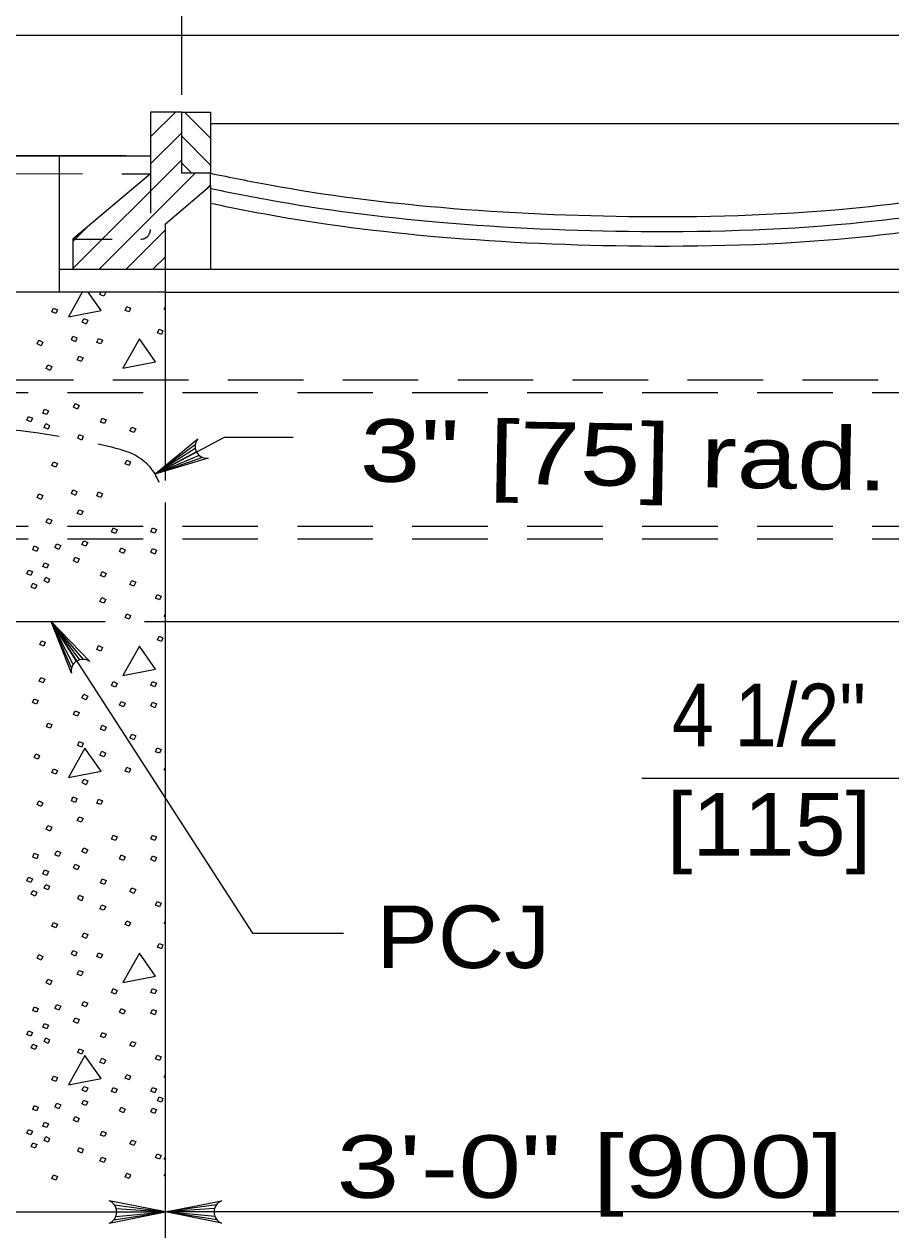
# Model space of a CAD drawing. Extents: x -1431.2 to -1397.2, y -1045.1 to -1001.1.
# Drawn here: x -1420.547 to -1418.346, y -1019.579 to -1016.517 of the extents above; entities that cross this region are included whole.
import ezdxf
from ezdxf.enums import TextEntityAlignment as Align

# ---------------------------------------------------------------- set-up
doc = ezdxf.new("R2010")
doc.units = 0
doc.header["$LTSCALE"] = 0.064
for name, pattern in [('LONG_DASHED', [7.5, 6, -1.5]), ('MEDIUM_DASHED', [4.5, 3, -1.5]), ('SHORT_DASHED', [2.7, 1.5, -1.2])]:
    doc.linetypes.add(name, pattern=pattern)
doc.layers.add('1', color=7, linetype='Continuous', lineweight=13)

msp = doc.modelspace()

# ---------------------------------------------------------------- linework, layer by layer
at = {"layer": '1'}
for p, q in [((-1420.147, -1016.69683), (-1420.147, -1016.11292)), ((-1420.22625, -1016.80383), (-1420.163, -1016.74058)), ((-1420.07358, -1016.80692), (-1420.14, -1016.74058)), ((-1420.22625, -1016.87233), (-1420.147, -1016.793)), ((-1420.07358, -1016.8755), (-1420.147, -1016.80208)), ((-1420.42342, -1017.13792), (-1420.147, -1016.8615)), ((-1420.12158, -1016.896), (-1420.147, -1016.87058)), ((-1420.35675, -1017.13975), (-1420.11292, -1016.896)), ((-1420.07358, -1016.896), (-1420.147, -1016.896)), ((-1420.08667, -1016.93817), (-1420.07358, -1016.92508)), ((-1420.42342, -1017.06942), (-1420.38458, -1017.03067)), ((-1420.28833, -1017.13975), (-1420.18825, -1017.03975)), ((-1420.21983, -1017.13975), (-1420.18825, -1017.10817)), ((-1420.11267, -1017.58558), (-1420.21558, -1017.65967)), ((-1420.11242, -1017.59525), (-1420.21558, -1017.65967)), ((-1420.10942, -1017.60375), (-1420.21558, -1017.65967)), ((-1420.10217, -1017.61267), (-1420.21558, -1017.65967)), ((-1420.09417, -1017.61767), (-1420.21558, -1017.65967)), ((-1420.41392, -1018.13508), (-1420.47867, -1018.03408)), ((-1420.42225, -1018.14308), (-1420.47867, -1018.03408)), ((-1420.4265, -1018.1515), (-1420.47867, -1018.03408)), ((-1420.40575, -1018.13142), (-1420.47867, -1018.03408)), ((-1420.39617, -1018.13033), (-1420.47867, -1018.03408)), ((-1418.97808, -1018.43242), (-1417.79208, -1018.43242)), ((-1421.59133, -1019.53367), (-1420.18825, -1019.53367)), ((-1420.31917, -1019.55367), (-1420.18825, -1019.53367)), ((-1420.31758, -1019.51558), (-1420.18825, -1019.53367)), ((-1420.31417, -1019.54533), (-1420.18825, -1019.53367)), ((-1420.31325, -1019.52458), (-1420.18825, -1019.53367)), ((-1420.31192, -1019.53367), (-1420.18825, -1019.53367)), ((-1420.05892, -1019.51558), (-1420.18825, -1019.53367)), ((-1420.06325, -1019.52458), (-1420.18825, -1019.53367)), ((-1417.79208, -1019.53367), (-1420.18825, -1019.53367)), ((-1420.06458, -1019.53367), (-1420.18825, -1019.53367)), ((-1420.06233, -1019.54533), (-1420.18825, -1019.53367)), ((-1420.05733, -1019.55367), (-1420.18825, -1019.53367))]:
    msp.add_line(p, q, dxfattribs=at)
at = {"layer": '1', "lineweight": 25}
for p, q in [((-1420.07358, -1016.76975), (-1417.85858, -1016.76975)), ((-1420.28933, -1016.85133), (-1421.04217, -1016.85133)), ((-1420.45767, -1017.19833), (-1420.45767, -1016.85133)), ((-1420.07358, -1016.927), (-1420.07358, -1017.13975)), ((-1420.45767, -1017.13975), (-1420.42342, -1017.13975)), ((-1420.18825, -1017.13975), (-1417.85858, -1017.13975)), ((-1420.18825, -1017.19833), (-1417.79208, -1017.19833)), ((-1420.18825, -1017.67583), (-1420.18825, -1017.19833)), ((-1420.18825, -1019.77192), (-1420.18825, -1017.73225)), ((-1420.18825, -1018.03408), (-1417.79208, -1018.03408))]:
    msp.add_line(p, q, dxfattribs=at)
at = {"layer": '1', "linetype": 'LONG_DASHED', "lineweight": 25}
for p, q in [((-1421.267, -1016.89492), (-1420.22625, -1016.89758)), ((-1420.72517, -1018.03408), (-1420.18825, -1018.03408))]:
    msp.add_line(p, q, dxfattribs=at)
at = {"layer": '1', "linetype": 'SHORT_DASHED', "lineweight": 25}
for p, q in [((-1420.22625, -1016.89758), (-1420.22625, -1017.03908)), ((-1420.42342, -1017.06325), (-1420.25042, -1017.06325))]:
    msp.add_line(p, q, dxfattribs=at)
at = {"layer": '1', "linetype": 'MEDIUM_DASHED'}
for p, q in [((-1423.35717, -1017.45292), (-1414.62608, -1017.45292)), ((-1423.35717, -1017.79175), (-1414.62608, -1017.79175)), ((-1423.35717, -1017.824), (-1414.62608, -1017.824))]:
    msp.add_line(p, q, dxfattribs=at)
at = {"layer": '1', "lineweight": 25}
for points in [[(-1414.98508, -1017.33992), (-1414.98508, -1016.54658), (-1422.97483, -1016.54658)], [(-1426.94317, -1016.69625), (-1422.97483, -1016.85133), (-1420.22625, -1016.85133)], [(-1420.147, -1016.74058), (-1420.22625, -1016.74058), (-1420.22625, -1016.89758), (-1420.42342, -1017.06325), (-1420.42342, -1017.13975), (-1420.18825, -1017.13975)], [(-1420.147, -1016.896), (-1420.147, -1016.74058), (-1420.07358, -1016.74058), (-1420.07358, -1016.896)], [(-1420.18825, -1017.19833), (-1420.18825, -1017.02442), (-1420.07358, -1016.927), (-1420.07358, -1016.896)], [(-1420.18825, -1017.19833), (-1420.72517, -1017.19833), (-1420.72517, -1020.93208), (-1417.26308, -1020.93208), (-1417.26308, -1017.19833)]]:
    msp.add_lwpolyline(points, dxfattribs=at)
at = {"layer": '1'}
for points in [[(-1420.39967, -1017.19833), (-1420.43458, -1017.26083), (-1420.35183, -1017.24475), (-1420.38442, -1017.19833)], [(-1420.33975, -1017.19833), (-1420.3445, -1017.20775), (-1420.35458, -1017.20367), (-1420.35208, -1017.19833)], [(-1420.203, -1017.19833), (-1420.20325, -1017.199), (-1420.20492, -1017.19833)], [(-1420.18825, -1017.2425), (-1420.19117, -1017.24133), (-1420.18825, -1017.23558)], [(-1420.21558, -1017.65967), (-1420.03842, -1017.56633), (-1419.86408, -1017.56633)], [(-1420.08, -1017.61958), (-1420.21558, -1017.65967), (-1420.10583, -1017.5705)], [(-1420.42725, -1018.16583), (-1420.47867, -1018.03408), (-1420.3805, -1018.13583)], [(-1420.47867, -1018.03408), (-1419.96675, -1018.82575), (-1419.73592, -1018.82575)], [(-1420.18825, -1018.02242), (-1420.19117, -1018.02125), (-1420.18825, -1018.0155)], [(-1420.18825, -1018.41242), (-1420.19117, -1018.41125), (-1420.18825, -1018.4055)], [(-1420.18825, -1018.80233), (-1420.19117, -1018.80125), (-1420.18825, -1018.79542)], [(-1420.18825, -1019.19233), (-1420.19117, -1019.19117), (-1420.18825, -1019.18542)], [(-1420.18825, -1019.40067), (-1420.19117, -1019.3995), (-1420.18825, -1019.39375)], [(-1420.18825, -1019.443), (-1420.19117, -1019.44183), (-1420.18825, -1019.43608)], [(-1420.33117, -1019.56225), (-1420.18825, -1019.53367), (-1420.33117, -1019.50508)], [(-1420.04533, -1019.56225), (-1420.18825, -1019.53367), (-1420.04533, -1019.50508)]]:
    msp.add_lwpolyline(points, dxfattribs=at)
for points in [[(-1420.47225, -1017.23867), (-1420.46217, -1017.24267), (-1420.46683, -1017.25208), (-1420.47692, -1017.24808)], [(-1420.28667, -1017.23467), (-1420.27658, -1017.23867), (-1420.28058, -1017.24808), (-1420.29067, -1017.24408)], [(-1420.39558, -1017.26492), (-1420.3855, -1017.26892), (-1420.3895, -1017.279), (-1420.39958, -1017.27433)], [(-1420.20458, -1017.29175), (-1420.1945, -1017.29583), (-1420.19858, -1017.30525), (-1420.20867, -1017.30117)], [(-1420.50992, -1017.32), (-1420.49983, -1017.32475), (-1420.50383, -1017.33417), (-1420.51392, -1017.32942)], [(-1420.42317, -1017.30992), (-1420.41308, -1017.314), (-1420.41708, -1017.32408), (-1420.42717, -1017.31933)], [(-1420.35858, -1017.31533), (-1420.3485, -1017.32), (-1420.3525, -1017.32942), (-1420.36258, -1017.32542)], [(-1420.25433, -1017.31667), (-1420.29608, -1017.39133), (-1420.21333, -1017.37517)], [(-1420.40767, -1017.36033), (-1420.39758, -1017.36442), (-1420.40233, -1017.37383), (-1420.41242, -1017.36975)], [(-1420.487, -1017.38258), (-1420.47692, -1017.38658), (-1420.481, -1017.39667), (-1420.49108, -1017.392)], [(-1420.41775, -1017.48075), (-1420.40767, -1017.48542), (-1420.41167, -1017.49483), (-1420.42183, -1017.49017)], [(-1420.53608, -1017.51367), (-1420.526, -1017.51767), (-1420.53008, -1017.52708), (-1420.54017, -1017.52308)], [(-1420.49575, -1017.49483), (-1420.48567, -1017.49958), (-1420.48967, -1017.50892), (-1420.49983, -1017.50492)], [(-1420.34917, -1017.51767), (-1420.33908, -1017.52242), (-1420.34308, -1017.53183), (-1420.35317, -1017.52775)], [(-1420.49242, -1017.53183), (-1420.48233, -1017.5365), (-1420.48633, -1017.54592), (-1420.49642, -1017.54125)], [(-1420.27383, -1017.54058), (-1420.26375, -1017.54458), (-1420.2685, -1017.55467), (-1420.27858, -1017.55)], [(-1420.407, -1017.55942), (-1420.39692, -1017.56342), (-1420.40092, -1017.5735), (-1420.411, -1017.56883)], [(-1420.47225, -1017.62867), (-1420.46217, -1017.63267), (-1420.46683, -1017.64208), (-1420.47692, -1017.63808)], [(-1420.28667, -1017.62458), (-1420.27658, -1017.62867), (-1420.28058, -1017.63808), (-1420.29067, -1017.634)], [(-1420.42317, -1017.69992), (-1420.41308, -1017.70392), (-1420.41708, -1017.714), (-1420.42717, -1017.70933)], [(-1420.35858, -1017.70525), (-1420.3485, -1017.71), (-1420.3525, -1017.71942), (-1420.36258, -1017.71533)], [(-1420.50992, -1017.71), (-1420.49983, -1017.71467), (-1420.50383, -1017.72408), (-1420.51392, -1017.71942)], [(-1420.40767, -1017.75033), (-1420.39758, -1017.75433), (-1420.40233, -1017.76375), (-1420.41242, -1017.75975)], [(-1420.487, -1017.7725), (-1420.47692, -1017.77658), (-1420.481, -1017.78667), (-1420.49108, -1017.78192)], [(-1420.32092, -1017.79675), (-1420.31083, -1017.80142), (-1420.31492, -1017.81083), (-1420.325, -1017.80683)], [(-1420.22075, -1017.79675), (-1420.21067, -1017.80075), (-1420.21533, -1017.81017), (-1420.22542, -1017.80617)], [(-1420.52133, -1017.84242), (-1420.51125, -1017.84717), (-1420.51525, -1017.85658), (-1420.52533, -1017.8525)], [(-1420.46417, -1017.83708), (-1420.45408, -1017.84108), (-1420.45875, -1017.85117), (-1420.46883, -1017.8465)], [(-1420.39558, -1017.829), (-1420.3855, -1017.83367), (-1420.39017, -1017.84308), (-1420.40025, -1017.83842)], [(-1420.30075, -1017.84717), (-1420.29067, -1017.85183), (-1420.29467, -1017.86125), (-1420.30475, -1017.85658)], [(-1420.22075, -1017.84917), (-1420.21067, -1017.85317), (-1420.21533, -1017.86325), (-1420.22542, -1017.85858)], [(-1420.49575, -1017.88483), (-1420.48567, -1017.8895), (-1420.48967, -1017.89892), (-1420.49983, -1017.89492)], [(-1420.41775, -1017.87067), (-1420.40767, -1017.87542), (-1420.41167, -1017.88483), (-1420.42183, -1017.88008)], [(-1420.53608, -1017.90367), (-1420.526, -1017.90767), (-1420.53008, -1017.91708), (-1420.54017, -1017.91308)], [(-1420.34917, -1017.90767), (-1420.33908, -1017.91233), (-1420.34308, -1017.92175), (-1420.35317, -1017.91775)], [(-1420.52533, -1017.93725), (-1420.51525, -1017.94192), (-1420.51933, -1017.95133), (-1420.52942, -1017.94667)], [(-1420.49242, -1017.92175), (-1420.48233, -1017.9265), (-1420.48633, -1017.93592), (-1420.49642, -1017.93117)], [(-1420.27383, -1017.9305), (-1420.26375, -1017.93458), (-1420.2685, -1017.94467), (-1420.27858, -1017.93992)], [(-1420.34983, -1017.97358), (-1420.33975, -1017.97825), (-1420.3445, -1017.98767), (-1420.35458, -1017.98367)], [(-1420.20933, -1017.9655), (-1420.19925, -1017.9695), (-1420.20325, -1017.97892), (-1420.21333, -1017.97492)], [(-1420.28667, -1018.01458), (-1420.27658, -1018.01858), (-1420.28058, -1018.028), (-1420.29067, -1018.024)], [(-1420.20458, -1018.07175), (-1420.1945, -1018.07575), (-1420.19858, -1018.08517), (-1420.20867, -1018.08117)], [(-1420.50342, -1018.083), (-1420.49333, -1018.08708), (-1420.49733, -1018.0965), (-1420.50742, -1018.09242)], [(-1420.35858, -1018.09525), (-1420.3485, -1018.09992), (-1420.3525, -1018.10933), (-1420.36258, -1018.10533)], [(-1420.25433, -1018.09658), (-1420.29608, -1018.17125), (-1420.21333, -1018.15508)], [(-1420.505, -1018.17625), (-1420.49492, -1018.18025), (-1420.49892, -1018.18967), (-1420.509, -1018.18567)], [(-1420.32092, -1018.18667), (-1420.31083, -1018.19142), (-1420.31492, -1018.20083), (-1420.325, -1018.19675)], [(-1420.22075, -1018.18667), (-1420.21067, -1018.19075), (-1420.21533, -1018.20017), (-1420.22542, -1018.19608)], [(-1420.39558, -1018.219), (-1420.3855, -1018.22367), (-1420.39017, -1018.23308), (-1420.40025, -1018.22833)], [(-1420.52192, -1018.23067), (-1420.51183, -1018.23475), (-1420.51583, -1018.24417), (-1420.52592, -1018.24008)], [(-1420.30075, -1018.23708), (-1420.29067, -1018.24183), (-1420.29467, -1018.25125), (-1420.30475, -1018.2465)], [(-1420.22075, -1018.23917), (-1420.21067, -1018.24317), (-1420.21533, -1018.25325), (-1420.22542, -1018.24858)], [(-1420.41775, -1018.26067), (-1420.40767, -1018.26533), (-1420.41167, -1018.27475), (-1420.42183, -1018.27008)], [(-1420.48658, -1018.292), (-1420.4765, -1018.296), (-1420.4805, -1018.30542), (-1420.49058, -1018.30133)], [(-1420.34917, -1018.29767), (-1420.33908, -1018.30233), (-1420.34308, -1018.31175), (-1420.35317, -1018.30775)], [(-1420.407, -1018.33933), (-1420.39692, -1018.34333), (-1420.40092, -1018.35342), (-1420.411, -1018.34875)], [(-1420.27383, -1018.3205), (-1420.26375, -1018.3245), (-1420.2685, -1018.33458), (-1420.27858, -1018.32992)], [(-1420.51783, -1018.37025), (-1420.50775, -1018.37425), (-1420.51175, -1018.38367), (-1420.52183, -1018.37967)], [(-1420.39292, -1018.35608), (-1420.43458, -1018.43075), (-1420.35183, -1018.41458)], [(-1420.34983, -1018.3635), (-1420.33975, -1018.36825), (-1420.3445, -1018.37767), (-1420.35458, -1018.37358)], [(-1420.20933, -1018.35542), (-1420.19925, -1018.3595), (-1420.20325, -1018.36892), (-1420.21333, -1018.36483)], [(-1420.47225, -1018.40858), (-1420.46217, -1018.41258), (-1420.46683, -1018.422), (-1420.47692, -1018.418)], [(-1420.28667, -1018.4045), (-1420.27658, -1018.40858), (-1420.28058, -1018.418), (-1420.29067, -1018.41392)], [(-1420.39558, -1018.43475), (-1420.3855, -1018.43883), (-1420.3895, -1018.44892), (-1420.39958, -1018.44417)], [(-1420.50992, -1018.48992), (-1420.49983, -1018.49458), (-1420.50383, -1018.504), (-1420.51392, -1018.49933)], [(-1420.42317, -1018.47983), (-1420.41308, -1018.48383), (-1420.41708, -1018.49392), (-1420.42717, -1018.48925)], [(-1420.35858, -1018.48525), (-1420.3485, -1018.48992), (-1420.3525, -1018.49933), (-1420.36258, -1018.49533)], [(-1420.40767, -1018.53025), (-1420.39758, -1018.53433), (-1420.40233, -1018.54367), (-1420.41242, -1018.53967)], [(-1420.487, -1018.55242), (-1420.47692, -1018.5565), (-1420.481, -1018.56658), (-1420.49108, -1018.56183)], [(-1420.32092, -1018.57667), (-1420.31083, -1018.58133), (-1420.31492, -1018.59075), (-1420.325, -1018.58675)], [(-1420.22075, -1018.57667), (-1420.21067, -1018.58067), (-1420.21533, -1018.59008), (-1420.22542, -1018.58608)], [(-1420.52133, -1018.62233), (-1420.51125, -1018.62708), (-1420.51525, -1018.6365), (-1420.52533, -1018.63242)], [(-1420.46417, -1018.617), (-1420.45408, -1018.621), (-1420.45875, -1018.63108), (-1420.46883, -1018.62642)], [(-1420.39558, -1018.60892), (-1420.3855, -1018.61367), (-1420.39017, -1018.62308), (-1420.40025, -1018.61833)], [(-1420.41775, -1018.65058), (-1420.40767, -1018.65533), (-1420.41167, -1018.66475), (-1420.42183, -1018.66)], [(-1420.30075, -1018.62708), (-1420.29067, -1018.63175), (-1420.29467, -1018.64117), (-1420.30475, -1018.6365)], [(-1420.22075, -1018.62908), (-1420.21067, -1018.63317), (-1420.21533, -1018.64325), (-1420.22542, -1018.6385)], [(-1420.53608, -1018.68358), (-1420.526, -1018.68758), (-1420.53008, -1018.697), (-1420.54017, -1018.693)], [(-1420.49575, -1018.66475), (-1420.48567, -1018.66942), (-1420.48967, -1018.67883), (-1420.49983, -1018.67483)], [(-1420.49242, -1018.70175), (-1420.48233, -1018.70642), (-1420.48633, -1018.71583), (-1420.49642, -1018.71108)], [(-1420.34917, -1018.68758), (-1420.33908, -1018.69233), (-1420.34308, -1018.70175), (-1420.35317, -1018.69767)], [(-1420.27383, -1018.71042), (-1420.26375, -1018.7145), (-1420.2685, -1018.72458), (-1420.27858, -1018.71983)], [(-1420.52533, -1018.71717), (-1420.51525, -1018.72192), (-1420.51933, -1018.73133), (-1420.52942, -1018.72658)], [(-1420.407, -1018.72925), (-1420.39692, -1018.73333), (-1420.40092, -1018.74342), (-1420.411, -1018.73867)], [(-1420.20933, -1018.74542), (-1420.19925, -1018.74942), (-1420.20325, -1018.75883), (-1420.21333, -1018.75483)], [(-1420.34983, -1018.7535), (-1420.33975, -1018.75817), (-1420.3445, -1018.76758), (-1420.35458, -1018.76358)], [(-1420.47225, -1018.7985), (-1420.46217, -1018.80258), (-1420.46683, -1018.812), (-1420.47692, -1018.80792)], [(-1420.28667, -1018.7945), (-1420.27658, -1018.7985), (-1420.28058, -1018.80792), (-1420.29067, -1018.80392)], [(-1420.39558, -1018.82475), (-1420.3855, -1018.82875), (-1420.3895, -1018.83883), (-1420.39958, -1018.83417)], [(-1420.20458, -1018.85167), (-1420.1945, -1018.85567), (-1420.19858, -1018.86508), (-1420.20867, -1018.86108)], [(-1420.50992, -1018.87992), (-1420.49983, -1018.88458), (-1420.50383, -1018.894), (-1420.51392, -1018.88933)], [(-1420.42317, -1018.86983), (-1420.41308, -1018.87383), (-1420.41708, -1018.88392), (-1420.42717, -1018.87925)], [(-1420.35858, -1018.87517), (-1420.3485, -1018.87992), (-1420.3525, -1018.88933), (-1420.36258, -1018.88525)], [(-1420.25433, -1018.8765), (-1420.29608, -1018.95117), (-1420.21333, -1018.935)], [(-1420.40767, -1018.92025), (-1420.39758, -1018.92425), (-1420.40233, -1018.93367), (-1420.41242, -1018.92967)], [(-1420.487, -1018.94242), (-1420.47692, -1018.94642), (-1420.481, -1018.9565), (-1420.49108, -1018.95183)], [(-1420.32092, -1018.96658), (-1420.31083, -1018.97133), (-1420.31492, -1018.98075), (-1420.325, -1018.97667)], [(-1420.22075, -1018.96658), (-1420.21067, -1018.97067), (-1420.21533, -1018.98008), (-1420.22542, -1018.976)], [(-1420.52133, -1019.01233), (-1420.51125, -1019.01708), (-1420.51525, -1019.02642), (-1420.52533, -1019.02242)], [(-1420.46417, -1019.007), (-1420.45408, -1019.011), (-1420.45875, -1019.02108), (-1420.46883, -1019.01633)], [(-1420.39558, -1018.99892), (-1420.3855, -1019.00358), (-1420.39017, -1019.013), (-1420.40025, -1019.00833)], [(-1420.30075, -1019.01708), (-1420.29067, -1019.02175), (-1420.29467, -1019.03117), (-1420.30475, -1019.02642)], [(-1420.22075, -1019.01908), (-1420.21067, -1019.02308), (-1420.21533, -1019.03317), (-1420.22542, -1019.0285)], [(-1420.41775, -1019.04058), (-1420.40767, -1019.04525), (-1420.41167, -1019.05467), (-1420.42183, -1019.05)], [(-1420.53608, -1019.0735), (-1420.526, -1019.07758), (-1420.53008, -1019.087), (-1420.54017, -1019.08292)], [(-1420.49575, -1019.05467), (-1420.48567, -1019.05942), (-1420.48967, -1019.06883), (-1420.49983, -1019.06475)], [(-1420.34917, -1019.07758), (-1420.33908, -1019.08225), (-1420.34308, -1019.09167), (-1420.35317, -1019.08767)], [(-1420.52533, -1019.10717), (-1420.51525, -1019.11183), (-1420.51933, -1019.12125), (-1420.52942, -1019.11658)], [(-1420.49242, -1019.09167), (-1420.48233, -1019.09642), (-1420.48633, -1019.10583), (-1420.49642, -1019.10108)], [(-1420.27383, -1019.10042), (-1420.26375, -1019.10442), (-1420.2685, -1019.1145), (-1420.27858, -1019.10983)], [(-1420.39292, -1019.13608), (-1420.43458, -1019.21067), (-1420.35183, -1019.19458)], [(-1420.407, -1019.11925), (-1420.39692, -1019.12325), (-1420.40092, -1019.13333), (-1420.411, -1019.12867)], [(-1420.34983, -1019.14342), (-1420.33975, -1019.14817), (-1420.3445, -1019.15758), (-1420.35458, -1019.1535)], [(-1420.20933, -1019.13542), (-1420.19925, -1019.13942), (-1420.20325, -1019.14883), (-1420.21333, -1019.14475)], [(-1420.47225, -1019.1885), (-1420.46217, -1019.1925), (-1420.46683, -1019.20192), (-1420.47692, -1019.19792)], [(-1420.28667, -1019.1845), (-1420.27658, -1019.1885), (-1420.28058, -1019.19792), (-1420.29067, -1019.19383)], [(-1420.39558, -1019.21475), (-1420.3855, -1019.21875), (-1420.3895, -1019.22883), (-1420.39958, -1019.22417)], [(-1420.32092, -1019.21725), (-1420.31083, -1019.222), (-1420.31492, -1019.23142), (-1420.325, -1019.22733)], [(-1420.22075, -1019.21725), (-1420.21067, -1019.22133), (-1420.21533, -1019.23075), (-1420.22542, -1019.22667)], [(-1420.52133, -1019.263), (-1420.51125, -1019.26767), (-1420.51525, -1019.27708), (-1420.52533, -1019.27308)], [(-1420.46417, -1019.25758), (-1420.45408, -1019.26167), (-1420.45875, -1019.27175), (-1420.46883, -1019.267)], [(-1420.39558, -1019.24958), (-1420.3855, -1019.25425), (-1420.39017, -1019.26367), (-1420.40025, -1019.259)], [(-1420.20458, -1019.24158), (-1420.1945, -1019.24567), (-1420.19858, -1019.25508), (-1420.20867, -1019.251)], [(-1420.41775, -1019.29125), (-1420.40767, -1019.29592), (-1420.41167, -1019.30533), (-1420.42183, -1019.30067)], [(-1420.30075, -1019.26767), (-1420.29067, -1019.27242), (-1420.29467, -1019.28183), (-1420.30475, -1019.27708)], [(-1420.22075, -1019.26975), (-1420.21067, -1019.27375), (-1420.21533, -1019.28383), (-1420.22542, -1019.27917)], [(-1420.53608, -1019.32417), (-1420.526, -1019.32825), (-1420.53008, -1019.33758), (-1420.54017, -1019.33358)], [(-1420.49575, -1019.30533), (-1420.48567, -1019.31008), (-1420.48967, -1019.3195), (-1420.49983, -1019.31542)], [(-1420.34917, -1019.32825), (-1420.33908, -1019.33292), (-1420.34308, -1019.34233), (-1420.35317, -1019.33833)], [(-1420.52533, -1019.35783), (-1420.51525, -1019.3625), (-1420.51933, -1019.37192), (-1420.52942, -1019.36717)], [(-1420.49242, -1019.34233), (-1420.48233, -1019.347), (-1420.48633, -1019.35642), (-1420.49642, -1019.35175)], [(-1420.27383, -1019.35108), (-1420.26375, -1019.35508), (-1420.2685, -1019.36517), (-1420.27858, -1019.3605)], [(-1420.407, -1019.36992), (-1420.39692, -1019.37392), (-1420.40092, -1019.384), (-1420.411, -1019.37933)], [(-1420.20933, -1019.386), (-1420.19925, -1019.39008), (-1420.20325, -1019.3995), (-1420.21333, -1019.39542)], [(-1420.34983, -1019.39408), (-1420.33975, -1019.39883), (-1420.3445, -1019.40825), (-1420.35458, -1019.40417)], [(-1420.47225, -1019.43917), (-1420.46217, -1019.44317), (-1420.46683, -1019.45258), (-1420.47692, -1019.44858)], [(-1420.28667, -1019.43508), (-1420.27658, -1019.43917), (-1420.28058, -1019.44858), (-1420.29067, -1019.4445)]]:
    msp.add_lwpolyline(points, close=True, dxfattribs=at)
at = {"layer": '1', "linetype": 'MEDIUM_DASHED'}
msp.add_lwpolyline([(-1423.35717, -1017.42058), (-1421.19792, -1017.42058), (-1414.62608, -1017.42058)], dxfattribs=at)
at = {"layer": '1'}
for centre, start, end in [((-1420.34269, -1019.53366), 292.08605, 67.91218), ((-1420.03383, -1019.53366), 112.08782, 247.91395)]:
    msp.add_arc(centre, 0.03084, start, end, dxfattribs=at)
at = {"layer": '1', "linetype": 'SHORT_DASHED', "lineweight": 25}
msp.add_ellipse((-1420.25046, -1017.03905), major_axis=(0.02421, 0), ratio=0.999895, start_param=4.712389, end_param=6.2831853, dxfattribs=at)
at = {"layer": '1'}
for centre, major_axis, start_param, end_param in [((-1420.08293, -1017.58978), (-0.02932, 0.00602), 5.7849266, 8.1555398), ((-1420.39779, -1018.16032), (0.018, 0.02392), 0.0294804, 2.4000935)]:
    msp.add_ellipse(centre, major_axis=major_axis, ratio=0.999895, start_param=start_param, end_param=end_param, dxfattribs=at)
at = {"layer": '1', "lineweight": 25}
for points in [[(-1420.07358, -1016.896), (-1419.92308, -1016.92558), (-1419.48892, -1016.9825), (-1418.98, -1017.00575), (-1418.41667, -1016.982), (-1417.85858, -1016.896)], [(-1420.07325, -1016.93475), (-1419.92917, -1016.96283), (-1419.49225, -1017.02017), (-1418.98008, -1017.04358), (-1418.413, -1017.01967), (-1417.85858, -1016.93425)], [(-1420.07342, -1016.97217), (-1419.93517, -1016.99933), (-1419.4955, -1017.057), (-1418.98008, -1017.0805), (-1418.40942, -1017.0565), (-1417.85858, -1016.97167)]]:
    msp.add_spline(points, degree=3, dxfattribs=at)
at = {"layer": '1', "linetype": 'MEDIUM_DASHED', "lineweight": 25}
msp.add_spline([(-1422.97483, -1017.33992), (-1422.42783, -1017.40283), (-1421.06567, -1017.52425), (-1420.3255, -1017.591), (-1420.24683, -1017.6235), (-1420.21467, -1017.66133), (-1420.19617, -1017.70508), (-1420.18708, -1017.73742)], degree=3, dxfattribs=at)

# ---------------------------------------------------------------- texts
at = {"layer": '1', "width": 1.3}
msp.add_text('3" [75] rad.', height=0.1588, rotation=359, dxfattribs=at).set_placement((-1419.69525, -1017.67817))
at = {"layer": '1'}
for s, width, p in [('4 1/2"', 0.9, (-1418.65529, -1018.35092)), ('[115]', 1.1, (-1418.65529, -1018.62875))]:
    msp.add_text(s, height=0.1588, dxfattribs=dict(at, width=width)).set_placement(p, align=Align.CENTER)
for s, width, p in [('PCJ', 1.1, (-1419.65217, -1018.91425)), ('3\'-0" [900]', 1.35, (-1419.75375, -1019.49783))]:
    msp.add_text(s, height=0.1588, dxfattribs=dict(at, width=width)).set_placement(p)

doc.saveas('drawing.dxf')
